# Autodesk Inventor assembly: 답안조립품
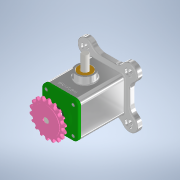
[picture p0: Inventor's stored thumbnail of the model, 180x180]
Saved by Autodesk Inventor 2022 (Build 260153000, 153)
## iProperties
Created: 2022-05
Part Number: 답안조립품
Document SubType Name: Assembly
Designer: Admin
Author: Admin
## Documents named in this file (11)
- C:\Users\Admin\Desktop\720509V1002\답안조립품.iam
- C:\Users\Admin\Desktop\720509V1002\본체.ipt
- C:\Users\Admin\Desktop\720509V1002\커버.ipt
- C:\Users\Admin\Desktop\720509V1002\편심축.ipt
- C:\Users\Admin\Desktop\720509V1002\베어링 6203.ipt
- C:\Users\Admin\Desktop\720509V1002\슬라이더.ipt
- C:\Users\Admin\Desktop\720509V1002\오일 실.ipt
- C:\Users\Admin\Desktop\720509V1002\부시.ipt
- C:\Users\Admin\Desktop\720509V1002\키 4 x 4 x 14.ipt
- C:\Users\Admin\Desktop\720509V1002\스프로킷.ipt
- C:\Users\Admin\Desktop\720509V1002\볼트 M4.ipt
